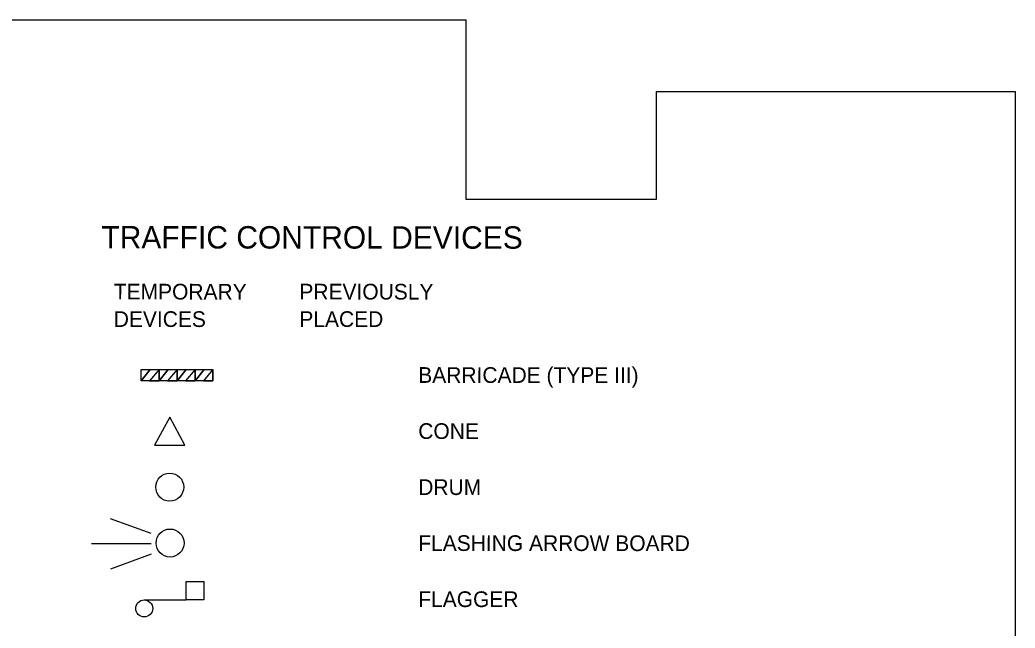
# Model space of a CAD drawing. Extents: x 2486454 to 2490507, y 369321 to 372999.
# Drawn here: x 2488062.6 to 2488506.6, y 370986.9 to 371258.3 of the extents above; entities that cross this region are included whole.
import ezdxf

# ---------------------------------------------------------------- set-up
doc = ezdxf.new("R2010")
doc.units = 0
for name, color, linetype in [('TC DEV BARRICADE', 7, 'Continuous'), ('TC DEV CONE', 7, 'Continuous'), ('TC DEV DRUM', 7, 'Continuous'), ('TC DEV FLAGGER', 7, 'Continuous'), ('TC DEV SIGN ARROW BOARD YELLOW', 7, 'Continuous'), ('TC SHEET LAYOUT SHAPE', 7, 'Continuous'), ('TC SHEET TEXT', 7, 'Continuous')]:
    doc.layers.add(name, color=color, linetype=linetype)

msp = doc.modelspace()

# ---------------------------------------------------------------- linework, layer by layer
at = {"layer": 'TC DEV BARRICADE'}
for p, q in [((2488120.7, 371102.29), (2488116.69, 371097.29)), ((2488116.69, 371097.29), (2488116.69, 371102.29)), ((2488116.69, 371102.29), (2488116.69, 371102.29)), ((2488116.69, 371102.29), (2488120.7, 371102.29)), ((2488124.69, 371102.29), (2488120.44, 371097.29)), ((2488124.69, 371097.29), (2488124.69, 371102.29)), ((2488124.69, 371102.29), (2488124.69, 371102.29)), ((2488128.7, 371102.29), (2488124.69, 371097.29)), ((2488124.69, 371097.29), (2488124.69, 371102.29)), ((2488124.69, 371102.29), (2488124.69, 371102.29)), ((2488124.69, 371102.29), (2488128.7, 371102.29)), ((2488132.69, 371102.29), (2488128.44, 371097.29)), ((2488132.69, 371097.29), (2488132.69, 371102.29)), ((2488132.69, 371102.29), (2488132.69, 371102.29)), ((2488136.7, 371102.29), (2488132.69, 371097.29)), ((2488132.69, 371097.29), (2488132.69, 371102.29)), ((2488132.69, 371102.29), (2488132.69, 371102.29)), ((2488132.69, 371102.29), (2488136.7, 371102.29)), ((2488140.69, 371102.29), (2488136.44, 371097.29)), ((2488140.69, 371097.29), (2488140.69, 371102.29)), ((2488140.69, 371102.29), (2488140.69, 371102.29)), ((2488144.7, 371102.29), (2488140.69, 371097.29)), ((2488140.69, 371097.29), (2488140.69, 371102.29)), ((2488140.69, 371102.29), (2488140.69, 371102.29)), ((2488140.69, 371102.29), (2488144.7, 371102.29)), ((2488148.69, 371102.29), (2488144.44, 371097.29)), ((2488148.69, 371097.29), (2488148.69, 371102.29)), ((2488148.69, 371102.29), (2488148.69, 371102.29)), ((2488120.44, 371097.29), (2488124.69, 371097.29)), ((2488128.44, 371097.29), (2488132.69, 371097.29)), ((2488136.44, 371097.29), (2488140.69, 371097.29)), ((2488144.44, 371097.29), (2488148.69, 371097.29))]:
    msp.add_line(p, q, dxfattribs=at)
for points in [[(2488124.69, 371102.29), (2488120.44, 371097.29), (2488116.69, 371097.29), (2488120.7, 371102.29)], [(2488124.69, 371102.29), (2488124.69, 371097.29), (2488116.69, 371097.29), (2488116.69, 371102.29)], [(2488132.69, 371102.29), (2488128.44, 371097.29), (2488124.69, 371097.29), (2488128.7, 371102.29)], [(2488132.69, 371102.29), (2488132.69, 371097.29), (2488124.69, 371097.29), (2488124.69, 371102.29)], [(2488140.69, 371102.29), (2488136.44, 371097.29), (2488132.69, 371097.29), (2488136.7, 371102.29)], [(2488140.69, 371102.29), (2488140.69, 371097.29), (2488132.69, 371097.29), (2488132.69, 371102.29)], [(2488148.69, 371102.29), (2488144.44, 371097.29), (2488140.69, 371097.29), (2488144.7, 371102.29)], [(2488148.69, 371102.29), (2488148.69, 371097.29), (2488140.69, 371097.29), (2488140.69, 371102.29)]]:
    msp.add_lwpolyline(points, close=True, dxfattribs=at)
at = {"layer": 'TC DEV CONE'}
msp.add_lwpolyline([(2488129.41, 371081.04), (2488122.61, 371068.54), (2488136.21, 371068.54)], close=True, dxfattribs=at)
at = {"layer": 'TC DEV DRUM'}
msp.add_circle((2488129.41, 371049.79), 6.25, dxfattribs=at)
msp.add_circle((2488129.41, 371049.79), 6.25, dxfattribs=at)
at = {"layer": 'TC DEV FLAGGER'}
msp.add_line((2488118.01, 370999.5), (2488136.77, 370999.5), dxfattribs=at)
msp.add_lwpolyline([(2488136.77, 370999.5), (2488136.77, 371007.67), (2488144.6, 371007.67), (2488144.6, 370999.5)], close=True, dxfattribs=at)
msp.add_circle((2488118.01, 370995.69), 3.79, dxfattribs=at)
at = {"layer": 'TC DEV SIGN ARROW BOARD YELLOW'}
for p, q in [((2488121.07, 371029.03), (2488103.02, 371035.6)), ((2488121.07, 371024.42), (2488094.52, 371024.42)), ((2488121.07, 371019.82), (2488103.02, 371013.25))]:
    msp.add_line(p, q, dxfattribs=at)
msp.add_circle((2488129.56, 371024.84), 6.25, dxfattribs=at)
at = {"layer": 'TC SHEET LAYOUT SHAPE'}
msp.add_lwpolyline([(2487016.56, 370666.84), (2487016.56, 370976.16), (2487016.56, 371248.27), (2487026.56, 371258.27), (2487469.58, 371258.27), (2487940.56, 371258.27), (2488261.56, 371258.27), (2488261.56, 371178.27), (2488346.56, 371178.27), (2488346.56, 371226.27), (2488506.56, 371226.27), (2488506.56, 370891.3), (2488506.56, 370612.1), (2488506.56, 370360.77), (2487778.38, 370360.77), (2487778.38, 370218.27), (2487608.92, 370218.27), (2487256.14, 370218.27), (2487016.56, 370218.27)], close=True, dxfattribs=at)

# ---------------------------------------------------------------- texts
at = {"layer": 'TC SHEET TEXT'}
for s, height, p in [('TRAFFIC CONTROL DEVICES', 10, (2488098.93, 371156.3)), ('TEMPORARY', 7, (2488104.45, 371133.53)), ('PREVIOUSLY', 7, (2488187.24, 371133.53)), ('DEVICES', 7, (2488104.44, 371121.28)), ('PLACED', 7, (2488187.23, 371121.28)), ('BARRICADE (TYPE III)', 7, (2488240.29, 371096.33)), ('CONE', 7, (2488240.29, 371071.3)), ('DRUM', 7, (2488240.29, 371046.3)), ('FLASHING ARROW BOARD', 7, (2488240.29, 371021.33)), ('FLAGGER', 7, (2488240.29, 370996.3))]:
    msp.add_text(s, height=height, rotation=359.9597, dxfattribs=at).set_placement(p)

doc.saveas('drawing.dxf')
